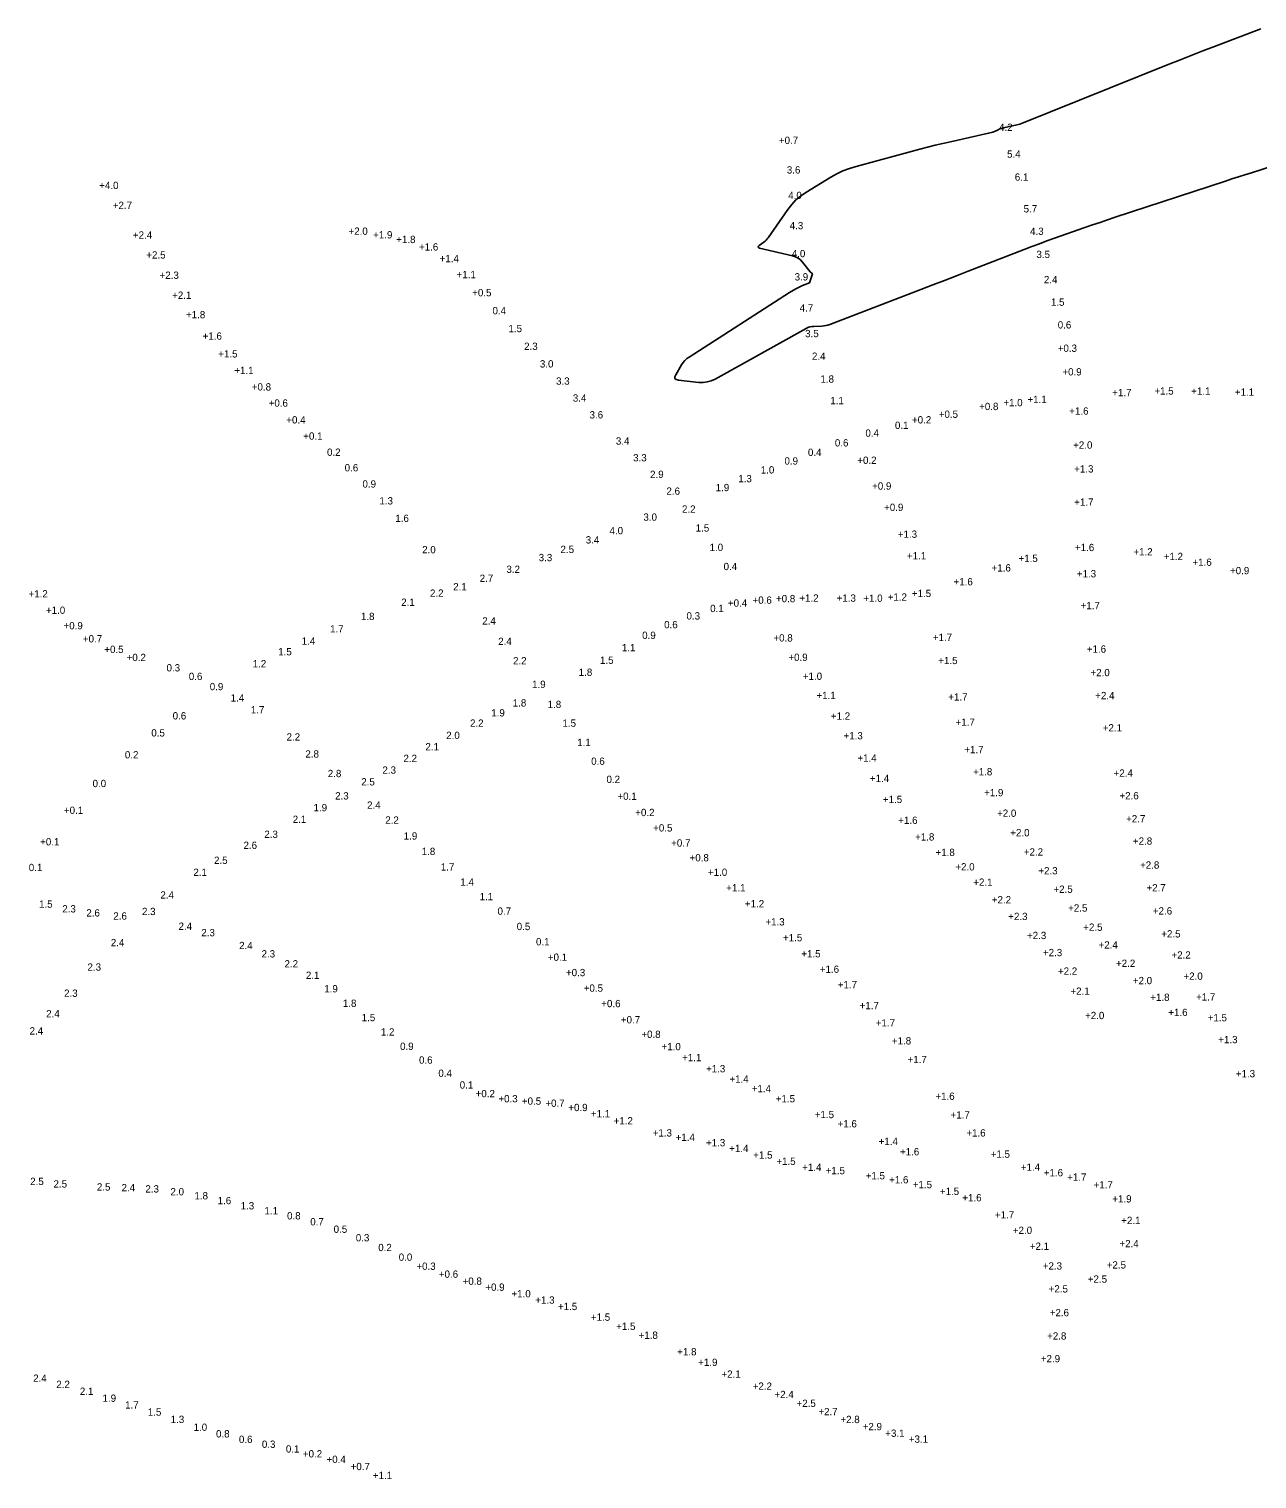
# Model space of a CAD drawing. Extents: x 837127 to 848654, y 3074248 to 3079868.
# Drawn here: x 843206 to 843732, y 3079028 to 3079649 of the extents above; entities that cross this region are included whole.
import ezdxf

# ---------------------------------------------------------------- set-up
doc = ezdxf.new("R2010")
doc.units = 0
doc.layers.add('V-HYDS-MAJR', color=7, linetype='Continuous')
doc.layers.add('V-HYDS-SOUN', color=7, linetype='Continuous')

msp = doc.modelspace()

# ---------------------------------------------------------------- linework, layer by layer
at = {"layer": 'V-HYDS-MAJR'}
msp.add_lwpolyline([(843744.65, 3079592.38), (843729.59, 3079587.64), (843726.81, 3079586.76), (843724.03, 3079585.87), (843721.26, 3079584.97), (843718.49, 3079584.07), (843671.27, 3079568.53), (843667.99, 3079567.44), (843664.73, 3079566.34), (843661.46, 3079565.23), (843658.21, 3079564.09), (843645.19, 3079559.53), (843641.94, 3079558.37), (843638.7, 3079557.19), (843635.47, 3079555.99), (843632.25, 3079554.75), (843608.24, 3079545.43), (843603.16, 3079543.46), (843598.09, 3079541.49), (843593.01, 3079539.54), (843587.93, 3079537.58), (843548.83, 3079522.57), (843548.01, 3079522.3), (843547.17, 3079522.09), (843546.33, 3079521.95), (843545.46, 3079521.88), (843541.98, 3079521.75), (843541.13, 3079521.67), (843540.3, 3079521.49), (843539.49, 3079521.22), (843538.72, 3079520.84), (843499.71, 3079499.19), (843498.04, 3079498.42), (843496.32, 3079497.92), (843494.54, 3079497.7), (843492.71, 3079497.76), (843483.96, 3079498.68), (843482.97, 3079498.92), (843482.45, 3079499.39), (843482.38, 3079500.09), (843482.78, 3079501.02), (843485.26, 3079505.21), (843485.93, 3079506.21), (843486.7, 3079507.11), (843487.57, 3079507.91), (843488.54, 3079508.62), (843531.56, 3079536.27), (843534.32, 3079537.9), (843537.19, 3079539.3), (843540.16, 3079540.46), (843541.4, 3079544.25), (843540.5, 3079545.14), (843537.16, 3079549.32), (843536.27, 3079550.27), (843535.26, 3079551.04), (843534.13, 3079551.62), (843532.89, 3079552.02), (843518.77, 3079555.35), (843518.29, 3079555.53), (843518.09, 3079555.76), (843518.18, 3079556.06), (843518.56, 3079556.41), (843520.64, 3079557.92), (843521.14, 3079558.32), (843521.6, 3079558.76), (843522.03, 3079559.23), (843522.42, 3079559.74), (843530.89, 3079571.93), (843532.52, 3079574.03), (843534.34, 3079575.94), (843536.35, 3079577.64), (843538.55, 3079579.14), (843549.25, 3079585.68), (843551.84, 3079587.14), (843554.51, 3079588.4), (843557.27, 3079589.47), (843560.11, 3079590.34), (843587.45, 3079597.7), (843590.74, 3079598.56), (843594.04, 3079599.39), (843597.35, 3079600.18), (843600.66, 3079600.93), (843616.9, 3079604.52), (843618.7, 3079605.02), (843620.4, 3079605.73), (843622, 3079606.64), (843630.31, 3079608.51), (843631.03, 3079608.71), (843693.92, 3079633.98), (843698.86, 3079635.95), (843703.82, 3079637.9), (843708.78, 3079639.82), (843713.76, 3079641.71), (843733.68, 3079649.25)], dxfattribs=at)

# ---------------------------------------------------------------- texts
at = {"layer": 'V-HYDS-SOUN'}
for s, p in [('4.2', (843621.43, 3079605.56)), ('+0.7 ', (843527.03, 3079599.96)), ('5.4', (843624.87, 3079594.07)), ('3.6', (843530.43, 3079587.28)), ('+4.0 ', (843235.64, 3079580.64)), ('6.1', (843628.17, 3079584.22)), ('+2.7 ', (843241.44, 3079572.09)), ('4.0', (843531.03, 3079576.34)), ('5.7', (843631.95, 3079570.6)), ('+2.0 ', (843342.5, 3079561.01)), ('4.3', (843531.67, 3079563.41)), ('4.3', (843634.72, 3079560.96)), ('+2.4 ', (843250.08, 3079559.35)), ('+1.9 ', (843353.06, 3079559.46)), ('+1.8 ', (843362.98, 3079557.47)), ('+1.6 ', (843372.73, 3079554.27)), ('+2.5 ', (843255.81, 3079550.83)), ('+1.4 ', (843381.58, 3079549.26)), ('4.0', (843532.56, 3079551.41)), ('3.5', (843637.45, 3079551.06)), ('+2.3 ', (843261.51, 3079542.13)), ('+1.1 ', (843388.85, 3079542.42)), ('3.9', (843533.78, 3079541.43)), ('2.4', (843640.65, 3079540.26)), ('+2.1 ', (843266.89, 3079533.56)), ('+0.5 ', (843395.54, 3079534.65)), ('1.5', (843643.67, 3079530.58)), ('+1.8 ', (843272.83, 3079525.22)), ('0.4', (843404.24, 3079526.93)), ('4.7', (843535.93, 3079528.08)), ('1.5', (843411.07, 3079519.27)), ('3.5', (843538.28, 3079517.12)), ('0.6', (843646.58, 3079520.84)), ('+1.6 ', (843279.96, 3079516.04)), ('2.3', (843417.8, 3079511.66)), ('+0.3 ', (843646.58, 3079510.83)), ('+1.5 ', (843286.67, 3079508.42)), ('3.0', (843424.55, 3079504.12)), ('2.4', (843541.2, 3079507.41)), ('+1.1 ', (843293.55, 3079501.31)), ('1.8', (843544.84, 3079497.61)), ('+0.9 ', (843648.58, 3079500.72)), ('+0.8 ', (843301.04, 3079494.25)), ('3.3', (843431.5, 3079496.75)), ('+1.7 ', (843669.95, 3079491.79)), ('+1.5 ', (843688.01, 3079492.51)), ('+1.1 ', (843703.82, 3079492.45)), ('+1.1 ', (843722.54, 3079492.02)), ('+0.6 ', (843308.28, 3079487.33)), ('3.4', (843438.68, 3079489.49)), ('1.1', (843549.06, 3079488.36)), ('+0.8 ', (843612.89, 3079485.86)), ('+1.0 ', (843623.27, 3079487.51)), ('+1.1 ', (843633.61, 3079488.89)), ('+0.4 ', (843315.83, 3079480.11)), ('3.6', (843445.85, 3079482.27)), ('+0.2 ', (843584.1, 3079480.13)), ('+0.5 ', (843595.57, 3079482.54)), ('+1.6 ', (843651.52, 3079483.91)), ('+0.1 ', (843323.11, 3079473.17)), ('0.4', (843564.13, 3079474.46)), ('0.1', (843576.79, 3079477.78)), ('3.4', (843457.14, 3079471.05)), ('0.6', (843551.03, 3079470.26)), ('+2.0 ', (843653.2, 3079469.31)), ('0.2', (843333.29, 3079466.25)), ('3.3', (843464.54, 3079463.87)), ('0.9', (843529.42, 3079462.49)), ('0.4', (843539.49, 3079466.2)), ('+0.2 ', (843560.65, 3079462.81)), ('0.6', (843340.85, 3079459.59)), ('2.9', (843471.81, 3079456.76)), ('1.3', (843509.61, 3079454.93)), ('1.0', (843519.26, 3079458.67)), ('+1.3 ', (843653.63, 3079459.1)), ('0.9', (843348.49, 3079452.63)), ('2.6', (843478.82, 3079449.57)), ('1.9', (843499.93, 3079451.1)), ('+0.9 ', (843567, 3079451.76)), ('1.3', (843355.75, 3079445.4)), ('2.2', (843485.49, 3079441.86)), ('+0.9 ', (843572.14, 3079442.62)), ('+1.7 ', (843653.67, 3079444.88)), ('1.6', (843362.57, 3079437.92)), ('3.0', (843468.95, 3079438.42)), ('4.0', (843454.42, 3079432.63)), ('1.5', (843491.35, 3079433.77)), ('+1.3 ', (843578.03, 3079431.11)), ('2.0', (843374.09, 3079424.47)), ('2.5', (843433.4, 3079424.6)), ('3.4', (843444.22, 3079428.67)), ('1.0', (843497.3, 3079425.45)), ('+1.6 ', (843653.97, 3079425.41)), ('+1.2 ', (843679.01, 3079423.55)), ('3.3', (843424.05, 3079421.08)), ('0.4', (843503.32, 3079417.25)), ('+1.1 ', (843581.94, 3079421.84)), ('+1.6 ', (843618.22, 3079416.66)), ('+1.5 ', (843629.77, 3079420.74)), ('+1.2 ', (843692.03, 3079421.55)), ('+1.6 ', (843704.36, 3079419.1)), ('2.7', (843398.75, 3079412.19)), ('3.2', (843410.21, 3079416.06)), ('+1.6 ', (843601.91, 3079410.72)), ('+1.3 ', (843654.79, 3079414.14)), ('+0.9 ', (843720.45, 3079415.49)), ('+1.2 ', (843205.31, 3079405.53)), ('2.2', (843377.43, 3079405.82)), ('2.1', (843387.4, 3079408.59)), ('+1.5 ', (843584.05, 3079405.7)), ('+1.0 ', (843212.79, 3079398.51)), ('2.1', (843365.09, 3079401.93)), ('0.1', (843497.57, 3079399.26)), ('+0.4 ', (843505.19, 3079401.57)), ('+0.6 ', (843515.74, 3079402.83)), ('+0.8 ', (843525.78, 3079403.49)), ('+1.2 ', (843535.8, 3079403.71)), ('+1.3 ', (843551.78, 3079403.7)), ('+1.0 ', (843563.24, 3079403.66)), ('+1.2 ', (843573.69, 3079404.15)), ('+1.7 ', (843656.4, 3079400.48)), ('+0.9 ', (843220.32, 3079391.89)), ('1.8', (843347.83, 3079395.86)), ('2.4', (843399.85, 3079393.92)), ('0.6', (843477.83, 3079392.32)), ('0.3', (843487.42, 3079396.07)), ('+0.7 ', (843228.62, 3079386.25)), ('1.7', (843334.6, 3079390.51)), ('0.9', (843468.41, 3079387.74)), ('+0.8 ', (843524.69, 3079386.64)), ('+1.7 ', (843593.03, 3079386.88)), ('+0.5 ', (843237.81, 3079381.72)), ('1.5', (843312.35, 3079380.71)), ('1.4', (843322.42, 3079385.26)), ('2.4', (843406.69, 3079385.17)), ('1.1', (843459.7, 3079382.46)), ('+1.6 ', (843659.06, 3079381.87)), ('+0.2 ', (843247.37, 3079378.25)), ('0.3', (843264.49, 3079373.81)), ('1.2', (843301.43, 3079375.55)), ('2.2', (843413.05, 3079376.84)), ('1.5', (843450.33, 3079377.07)), ('+0.9 ', (843531.1, 3079378.32)), ('+1.5 ', (843595.37, 3079376.95)), ('0.6', (843274.03, 3079370.14)), ('1.8', (843441.2, 3079371.91)), ('+1.0 ', (843537.3, 3079370.21)), ('+2.0 ', (843660.64, 3079371.77)), ('0.9', (843283.01, 3079365.76)), ('1.4', (843291.97, 3079360.91)), ('1.9', (843421.21, 3079366.71)), ('+1.1 ', (843543.14, 3079361.97)), ('+1.7 ', (843599.67, 3079361.31)), ('+2.4 ', (843662.66, 3079361.91)), ('1.7', (843300.63, 3079355.82)), ('1.9', (843403.69, 3079354.5)), ('1.8', (843412.91, 3079358.77)), ('1.8', (843427.88, 3079358.13)), ('0.6', (843267.11, 3079353.23)), ('2.2', (843394.6, 3079350.09)), ('1.5', (843434.24, 3079350.1)), ('+1.2 ', (843549.32, 3079353.12)), ('+1.7 ', (843602.79, 3079350.51)), ('0.5', (843257.96, 3079345.92)), ('2.2', (843315.95, 3079344.17)), ('2.0', (843384.4, 3079344.84)), ('+1.3 ', (843554.75, 3079344.7)), ('+2.1 ', (843665.89, 3079348.08)), ('0.2', (843246.62, 3079336.53)), ('2.8', (843324.02, 3079336.88)), ('2.1', (843375.48, 3079339.99)), ('1.1', (843440.56, 3079341.85)), ('+1.7 ', (843606.54, 3079338.77)), ('2.3', (843357.06, 3079329.96)), ('2.2', (843366.06, 3079334.97)), ('0.6', (843446.55, 3079333.77)), ('+1.4 ', (843560.69, 3079335.13)), (' 0.0', (843231.61, 3079324.22)), ('2.8', (843333.63, 3079328.49)), ('2.5', (843347.96, 3079324.93)), ('0.2', (843453.12, 3079325.99)), ('+1.4 ', (843566.07, 3079326.4)), ('+1.8 ', (843610.27, 3079329.24)), ('+2.4 ', (843670.54, 3079328.67)), ('2.3', (843336.76, 3079318.91)), ('+0.1 ', (843457.81, 3079318.75)), ('+1.5 ', (843571.63, 3079317.41)), ('+1.9 ', (843615.03, 3079320.3)), ('+2.6 ', (843673.05, 3079318.99)), ('+0.1 ', (843220.49, 3079312.74)), ('1.9', (843327.51, 3079313.88)), ('2.4', (843350.46, 3079314.95)), ('+0.2 ', (843465.45, 3079311.79)), ('+2.0 ', (843620.57, 3079311.48)), ('2.1', (843318.58, 3079308.86)), ('2.2', (843358.26, 3079308.53)), ('+0.5 ', (843473.13, 3079305.18)), ('+1.6 ', (843578.21, 3079308.44)), ('+2.7 ', (843675.91, 3079309.09)), ('+0.1 ', (843210.3, 3079299.25)), ('2.3', (843306.41, 3079302.45)), ('1.9', (843366.17, 3079301.72)), ('+0.7 ', (843480.85, 3079298.71)), ('+1.8 ', (843585.43, 3079301.33)), ('+2.0 ', (843626.24, 3079303.12)), ('+2.8 ', (843678.83, 3079299.52)), ('2.6', (843297.48, 3079297.72)), ('1.8', (843373.89, 3079295.09)), ('+0.8 ', (843488.74, 3079292.4)), ('+1.8 ', (843594.2, 3079294.68)), ('+2.2 ', (843632.05, 3079294.87)), ('0.1', (843205.42, 3079288.21)), ('2.1', (843275.99, 3079286.15)), ('2.5', (843284.85, 3079291.29)), ('1.7', (843382.09, 3079288.47)), ('+1.0 ', (843496.62, 3079286.16)), ('+2.0 ', (843602.68, 3079288.49)), ('+2.3 ', (843638.27, 3079286.82)), ('+2.8 ', (843681.89, 3079289.27)), ('1.4', (843390.44, 3079281.93)), ('+2.1 ', (843610.39, 3079281.91)), ('2.4', (843261.84, 3079276.42)), ('1.1', (843398.71, 3079275.71)), ('+1.1 ', (843504.46, 3079279.51)), ('+2.2 ', (843618.33, 3079274.37)), ('+2.5 ', (843644.74, 3079278.89)), ('+2.7 ', (843684.64, 3079279.54)), ('1.5', (843209.82, 3079272.5)), ('2.3', (843219.78, 3079270.48)), ('2.6', (843230.1, 3079268.74)), ('2.3', (843253.96, 3079269.35)), ('0.7', (843406.4, 3079269.5)), ('+1.2 ', (843512.47, 3079272.66)), ('+2.5 ', (843651.05, 3079270.84)), ('+2.6 ', (843687.37, 3079269.59)), ('2.6', (843241.67, 3079267.41)), ('2.4', (843269.63, 3079263.03)), ('0.5', (843414.62, 3079262.91)), ('+1.3 ', (843521.23, 3079264.91)), ('+2.3 ', (843625.38, 3079267.23)), ('+2.5 ', (843657.52, 3079262.61)), ('2.4', (843240.6, 3079256.02)), ('2.3', (843279.4, 3079260.28)), ('0.1', (843422.89, 3079256.38)), ('+1.5 ', (843528.79, 3079258.12)), ('+2.3 ', (843633.41, 3079259.06)), ('+2.5 ', (843690.99, 3079259.75)), ('2.4', (843295.61, 3079254.75)), ('2.3', (843305.22, 3079251.19)), ('+0.1 ', (843427.98, 3079249.75)), ('+1.5 ', (843536.65, 3079251.23)), ('+2.3 ', (843640.25, 3079251.73)), ('+2.4 ', (843664.08, 3079255.01)), ('+2.2 ', (843695.35, 3079250.69)), ('2.3', (843230.59, 3079245.53)), ('2.2', (843315.06, 3079246.89)), ('+0.3 ', (843435.74, 3079243.16)), ('+1.6 ', (843544.58, 3079244.59)), ('+2.2 ', (843646.69, 3079243.78)), ('+2.2 ', (843671.56, 3079247.12)), ('2.1', (843324.24, 3079242)), ('+0.5 ', (843443.36, 3079236.5)), ('+1.7 ', (843552.28, 3079237.96)), ('+2.0 ', (843678.79, 3079239.72)), ('+2.0 ', (843700.5, 3079241.62)), ('2.3', (843220.55, 3079234.31)), ('1.9', (843332.1, 3079236.22)), ('+2.1 ', (843652.02, 3079235.18)), ('+1.8 ', (843686.27, 3079232.56)), ('+1.7 ', (843705.88, 3079232.69)), ('2.4', (843212.88, 3079225.52)), ('1.8', (843340.09, 3079230)), ('+0.6 ', (843450.88, 3079229.87)), ('+1.7 ', (843561.66, 3079229.02)), ('+2.0 ', (843658.31, 3079224.75)), ('+1.6 ', (843694, 3079226.07)), ('2.4', (843205.77, 3079218.15)), ('1.5', (843348.16, 3079223.87)), ('+0.7 ', (843459.28, 3079222.94)), ('+1.7 ', (843568.58, 3079221.59)), ('+1.5 ', (843710.89, 3079223.82)), ('1.2', (843356.37, 3079217.7)), ('0.9', (843364.61, 3079211.55)), ('+0.8 ', (843468.07, 3079216.68)), ('+1.8 ', (843575.49, 3079213.88)), ('+1.3 ', (843715.42, 3079214.43)), ('0.6', (843372.74, 3079205.65)), ('+1.0 ', (843476.71, 3079211.41)), ('+1.1 ', (843485.54, 3079206.72)), ('+1.7 ', (843582.2, 3079205.88)), ('0.4', (843381.03, 3079200)), ('+1.3 ', (843495.79, 3079201.94)), ('+1.3 ', (843722.95, 3079199.8)), ('0.1', (843390.19, 3079194.96)), ('+1.4 ', (843505.81, 3079197.51)), ('+1.4 ', (843515.41, 3079193.39)), ('+0.2 ', (843397.01, 3079191.26)), ('+0.3 ', (843406.77, 3079189.08)), ('+0.5 ', (843416.85, 3079188.05)), ('+0.7 ', (843426.9, 3079187.15)), ('+1.5 ', (843525.7, 3079189.07)), ('+1.6 ', (843594.13, 3079190.15)), ('+0.9 ', (843436.75, 3079185.31)), ('+1.1 ', (843446.44, 3079182.66)), ('+1.5 ', (843542.42, 3079182.29)), ('+1.7 ', (843600.63, 3079182.11)), ('+1.2 ', (843456.18, 3079179.6)), ('+1.3 ', (843472.92, 3079174.42)), ('+1.6 ', (843552.21, 3079178.32)), ('+1.6 ', (843607.41, 3079174.42)), ('+1.4 ', (843482.76, 3079172.52)), ('+1.3 ', (843495.78, 3079170.21)), ('+1.4 ', (843569.8, 3079170.79)), ('+1.4 ', (843505.73, 3079167.79)), ('+1.5 ', (843516.04, 3079164.94)), ('+1.5 ', (843525.95, 3079162.23)), ('+1.6 ', (843578.96, 3079166.36)), ('+1.5 ', (843617.85, 3079165.31)), ('+1.4 ', (843537.02, 3079159.69)), ('+1.5 ', (843547.09, 3079158.25)), ('+1.5 ', (843564.25, 3079156.06)), ('+1.4 ', (843630.76, 3079159.72)), ('+1.6 ', (843640.6, 3079157.35)), ('2.5', (843206.03, 3079153.62)), ('2.5', (843216.02, 3079152.54)), ('2.5', (843234.62, 3079151.26)), ('2.4', (843245.2, 3079150.95)), ('2.3', (843255.41, 3079150.42)), ('+1.6 ', (843574.3, 3079154.35)), ('+1.5 ', (843584.43, 3079152.24)), ('+1.7 ', (843650.63, 3079155.46)), ('+1.7 ', (843661.97, 3079152.15)), ('2.0', (843266.16, 3079149.22)), ('1.8', (843276.45, 3079147.46)), ('1.6', (843286.39, 3079145.4)), ('1.3', (843296.26, 3079143.17)), ('+1.5 ', (843596.05, 3079149.36)), ('+1.6 ', (843605.68, 3079146.63)), ('+1.9 ', (843669.98, 3079146.14)), ('1.1', (843306.47, 3079141.03)), ('0.8', (843316.15, 3079138.87)), ('+1.7 ', (843619.67, 3079139.29)), ('+2.1 ', (843673.82, 3079136.9)), ('0.7', (843326.1, 3079136.33)), ('0.5', (843336.13, 3079133.14)), ('+2.0 ', (843627.35, 3079132.65)), ('0.3', (843345.63, 3079129.46)), ('0.2', (843355.25, 3079125.28)), ('+2.1 ', (843634.61, 3079125.83)), ('+2.4 ', (843673.05, 3079126.94)), (' 0.0', (843362.87, 3079121.15)), ('+0.3 ', (843371.6, 3079117.26)), ('+0.6 ', (843381.24, 3079113.87)), ('+2.3 ', (843640.17, 3079117.37)), ('+2.5 ', (843667.59, 3079117.82)), ('+0.8 ', (843391.43, 3079110.85)), ('+0.9 ', (843401.17, 3079108.29)), ('+2.5 ', (843642.7, 3079107.55)), ('+2.5 ', (843659.48, 3079111.74)), ('+1.0 ', (843412.37, 3079105.45)), ('+1.3 ', (843422.6, 3079102.77)), ('+1.5 ', (843432.31, 3079100)), ('+1.5 ', (843446.44, 3079095.43)), ('+2.6 ', (843643.15, 3079097.36)), ('+1.5 ', (843457.26, 3079091.49)), ('+1.8 ', (843466.89, 3079087.68)), ('+2.8 ', (843642.03, 3079087.35)), ('+1.8 ', (843483.44, 3079080.59)), ('+1.9 ', (843492.43, 3079076.07)), ('+2.9 ', (843639.35, 3079077.63)), ('2.4', (843207.3, 3079069.25)), ('+2.1 ', (843502.4, 3079071)), ('2.2', (843217.22, 3079066.6)), ('2.1', (843227.32, 3079063.66)), ('+2.2 ', (843515.8, 3079065.84)), ('1.9', (843237.04, 3079060.68)), ('1.7', (843246.73, 3079057.77)), ('+2.4 ', (843525.14, 3079062.26)), ('+2.5 ', (843534.61, 3079058.48)), ('1.5', (843256.44, 3079054.75)), ('1.3', (843266.26, 3079051.6)), ('+2.7 ', (843543.96, 3079054.92)), ('+2.8 ', (843553.42, 3079051.56)), ('1.0', (843276.08, 3079048.23)), ('0.8', (843285.7, 3079045.4)), ('+2.9 ', (843562.96, 3079048.5)), ('+3.1 ', (843572.64, 3079045.67)), ('0.6', (843295.52, 3079043.02)), ('0.3', (843305.37, 3079040.94)), ('0.1', (843315.65, 3079038.93)), ('+3.1 ', (843582.73, 3079043.13)), ('+0.2 ', (843322.94, 3079036.83)), ('+0.4 ', (843333.07, 3079034.45)), ('+0.7 ', (843343.42, 3079031.39)), ('+1.1 ', (843352.96, 3079027.59))]:
    msp.add_text(s, height=3.125, dxfattribs=at).set_placement(p)

doc.saveas('drawing.dxf')
